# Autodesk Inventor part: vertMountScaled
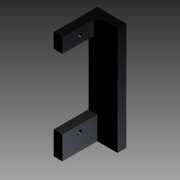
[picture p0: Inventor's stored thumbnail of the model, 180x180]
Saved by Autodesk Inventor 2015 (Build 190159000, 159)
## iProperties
Created: 2015-02
Part Number: vertMountScaled
Material: Generic
Document SubType Name: Modeling
Designer: sungeun
Density: 1 g/cm^3
Appearance: Default
Author: sungeun
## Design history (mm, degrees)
feature "vertMount"
feature "MeshFeature1"
body "Solid1"
